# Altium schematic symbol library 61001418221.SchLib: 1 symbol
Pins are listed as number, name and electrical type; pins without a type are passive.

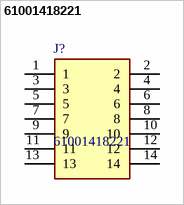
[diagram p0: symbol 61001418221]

## 61001418221
designator J?
WURTH ELEKTRONIK - 61001418221 - Board-To-Board Connector, 2.54 mm, 14 Contacts, Header, WR-PHD Series, Surface Mount, 1 Rows; Geometry.Height: 9.3mm
footprint 61001418221
pins: 1, 2, 3, 4, 5, 6, 7, 8, 9, 10, 11, 12, 13, 14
